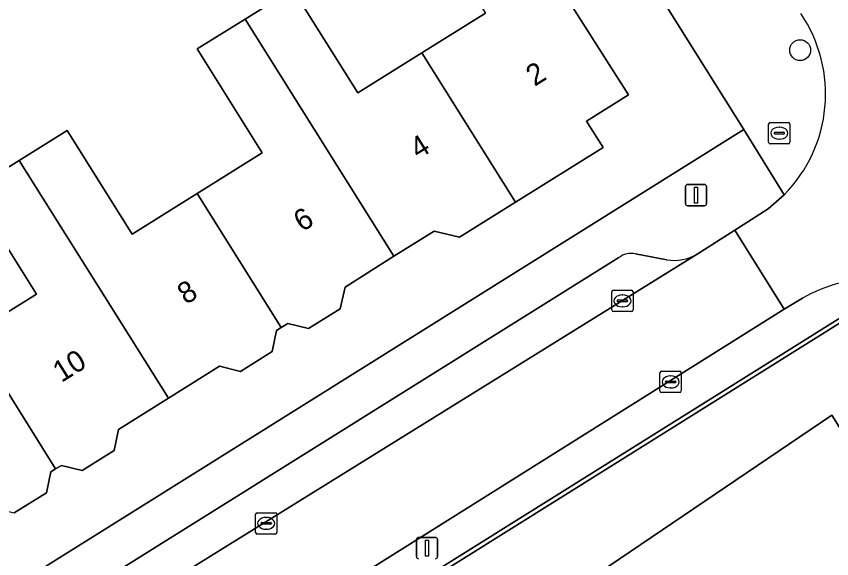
# Model space of a CAD drawing. Extents: x 159664 to 160323, y 385312 to 386115.
# Drawn here: x 159925.33 to 159963.61, y 385804.42 to 385829.91 of the extents above; entities that cross this region are included whole.
import ezdxf

# ---------------------------------------------------------------- set-up
doc = ezdxf.new("R2010")
doc.units = 0
for name, color, linetype in [('IMGEO_Boom', 7, 'Continuous'), ('IMGEO_Brandkraan', 7, 'Continuous'), ('IMGEO_Erf', 7, 'Continuous'), ('IMGEO_Groenvoorziening', 7, 'Continuous'), ('IMGEO_Kolk', 7, 'Continuous'), ('IMGEO_Lichtmast', 7, 'Continuous'), ('IMGEO_Pand', 7, 'Continuous'), ('IMGEO_Pand_nummerreeks', 7, 'Continuous'), ('IMGEO_Parkeervlak_open', 7, 'Continuous'), ('IMGEO_Rijbaan_lokaal_open', 7, 'Continuous'), ('IMGEO_Terreindeel_zand', 7, 'Continuous'), ('IMGEO_Voetpad_open', 7, 'Continuous')]:
    doc.layers.add(name, color=color, linetype=linetype)

msp = doc.modelspace()

# ---------------------------------------------------------------- linework, layer by layer
at = {"layer": 'IMGEO_Boom'}
msp.add_circle((159962.124, 385828.317), 0.489, dxfattribs=at)
at = {"layer": 'IMGEO_Brandkraan'}
for p, q in [((159960.645, 385823.99), (159960.645, 385824.842)), ((159960.72, 385824.916), (159961.572, 385824.916)), ((159961.133, 385824.696), (159961.158, 385824.696)), ((159961.646, 385824.842), (159961.646, 385823.99)), ((159960.904, 385824.41), (159960.904, 385824.422)), ((159961.342, 385824.373), (159960.944, 385824.373)), ((159960.947, 385824.459), (159961.345, 385824.459)), ((159961.388, 385824.422), (159961.388, 385824.41)), ((159961.572, 385823.916), (159960.72, 385823.916)), ((159961.156, 385824.136), (159961.131, 385824.136))]:
    msp.add_line(p, q, dxfattribs=at)
for points in [[(159960.645, 385823.99), (159960.645, 385824.842)], [(159960.72, 385824.916), (159961.572, 385824.916)], [(159961.646, 385824.842), (159961.646, 385823.99)], [(159961.572, 385823.916), (159960.72, 385823.916)]]:
    msp.add_lwpolyline(points, dxfattribs=at)
for centre, radius, start, end in [((159960.722, 385824.84), 0.0765, 91.552, 178.448), ((159960.722, 385824.84), 0.0765, 91.552, 178.448), ((159961.57, 385824.84), 0.0765, 1.552, 88.448), ((159961.57, 385824.84), 0.0765, 1.552, 88.448), ((159960.944, 385824.419), 0.0403, 85.8775, 175.7526), ((159960.941, 385824.409), 0.0366, 178.938, 274.7102), ((159961.345, 385824.416), 0.043, 264.8664, 352.4533), ((159961.349, 385824.421), 0.0386, 1.7309, 96.639), ((159960.722, 385823.992), 0.0765, 181.552, 268.448), ((159960.722, 385823.992), 0.0765, 181.552, 268.448), ((159961.57, 385823.992), 0.0765, 271.552, 358.448), ((159961.57, 385823.992), 0.0765, 271.552, 358.448)]:
    msp.add_arc(centre, radius, start, end, dxfattribs=at)
for centre, major_axis, ratio, start_param, end_param in [((159961.132, 385824.416), (-0.387, 0.002), 0.722429, 4.712389, 7.853982), ((159961.157, 385824.416), (-0.39, 0.002), 0.717154, 1.570796, 4.712389)]:
    msp.add_ellipse(centre, major_axis=major_axis, ratio=ratio, start_param=start_param, end_param=end_param, dxfattribs=at)
at = {"layer": 'IMGEO_Erf'}
for points in [[(159898.799, 385812.12), (159910.257, 385793.769), (159959.474, 385824.596), (159946.689, 385845.008)], [(159948.518, 385834.96), (159954.064, 385826.211), (159952.102, 385824.973), (159952.871, 385823.744), (159948.758, 385821.169), (159946.142, 385819.53), (159944.946, 385819.816), (159943.059, 385818.63), (159940.762, 385817.185), (159940.536, 385816.168), (159939.047, 385815.234), (159938.073, 385815.477), (159937.768, 385815.289), (159937.544, 385815.15), (159937.34, 385814.165), (159935.851, 385813.224), (159934.874, 385813.473), (159932.474, 385811.962), (159930.134, 385810.488), (159929.922, 385809.511), (159928.43, 385808.574), (159927.448, 385808.802), (159927.18, 385808.645), (159926.953, 385808.511), (159926.745, 385807.519), (159925.232, 385806.576)], [(159923.228, 385814.95), (159926.274, 385816.858), (159923.222, 385821.731), (159925.469, 385823.138), (159927.714, 385824.544), (159930.766, 385819.671), (159933.822, 385821.585), (159936.876, 385823.498), (159933.825, 385828.371), (159936.072, 385829.778), (159938.316, 385831.184), (159941.368, 385826.311), (159944.361, 385828.185), (159947.352, 385830.058)]]:
    msp.add_lwpolyline(points, dxfattribs=at)
at = {"layer": 'IMGEO_Groenvoorziening'}
for points in [[(159962.237, 385816.658), (159961.371, 385816.147), (159919.835, 385790.061), (159919.7, 385789.976), (159914.865, 385786.947), (159915.717, 385785.521), (159964.662, 385816.146)], [(159995.344, 385766.743), (159975.15, 385798.647), (159964.547, 385815.857), (159909.705, 385781.51)]]:
    msp.add_lwpolyline(points, dxfattribs=at)
for points in [[(159964.674, 385816.154), (159964.662, 385816.146), (159915.717, 385785.521), (159915.048, 385785.102), (159909.031, 385781.344), (159908.899, 385778.308), (159910.953, 385779.54), (159909.705, 385781.51), (159964.547, 385815.857), (159975.15, 385798.647), (159995.344, 385766.743), (159938.039, 385730.88), (159933.655, 385728.136), (159933.737, 385727.999), (159940.323, 385732.142), (159995.631, 385766.698)], [(159954.246, 385795.242), (159955.408, 385796.027), (159951.163, 385802.729), (159963.604, 385811.166), (159970.471, 385800.247), (159965.618, 385797.02), (159966.505, 385795.588), (159967.641, 385793.756), (159965.549, 385792.301), (159963.92, 385791.167), (159961.742, 385794.443), (159958.086, 385792.013), (159957.032, 385793.455), (159955.83, 385792.745)]]:
    msp.add_lwpolyline(points, close=True, dxfattribs=at)
msp.add_arc((159965.736, 385810.616), 6.982, 104.8122, 120.0758, dxfattribs=at)
at = {"layer": 'IMGEO_Kolk'}
for p, q in [((159953.359, 385817.036), (159954.211, 385817.036)), ((159953.284, 385816.11), (159953.284, 385816.962)), ((159953.772, 385816.816), (159953.797, 385816.816)), ((159954.285, 385816.962), (159954.285, 385816.11)), ((159953.543, 385816.53), (159953.543, 385816.542)), ((159953.981, 385816.493), (159953.583, 385816.493)), ((159953.586, 385816.579), (159953.984, 385816.579)), ((159953.795, 385816.256), (159953.77, 385816.256)), ((159954.027, 385816.542), (159954.027, 385816.53)), ((159954.211, 385816.036), (159953.359, 385816.036)), ((159955.545, 385812.303), (159955.545, 385813.155)), ((159955.62, 385813.229), (159956.472, 385813.229)), ((159956.546, 385813.155), (159956.546, 385812.303)), ((159955.847, 385812.772), (159956.245, 385812.772)), ((159956.033, 385813.009), (159956.058, 385813.009)), ((159955.804, 385812.723), (159955.804, 385812.735)), ((159956.242, 385812.686), (159955.844, 385812.686)), ((159956.056, 385812.449), (159956.031, 385812.449)), ((159956.288, 385812.735), (159956.288, 385812.723)), ((159956.472, 385812.229), (159955.62, 385812.229)), ((159936.561, 385805.658), (159936.561, 385806.51)), ((159936.636, 385806.584), (159937.488, 385806.584)), ((159937.049, 385806.364), (159937.074, 385806.364)), ((159937.562, 385806.51), (159937.562, 385805.658)), ((159936.82, 385806.078), (159936.82, 385806.09)), ((159937.258, 385806.041), (159936.86, 385806.041)), ((159936.863, 385806.127), (159937.261, 385806.127)), ((159937.304, 385806.09), (159937.304, 385806.078)), ((159937.488, 385805.584), (159936.636, 385805.584)), ((159937.072, 385805.804), (159937.047, 385805.804))]:
    msp.add_line(p, q, dxfattribs=at)
for points in [[(159953.359, 385817.036), (159954.211, 385817.036)], [(159953.284, 385816.11), (159953.284, 385816.962)], [(159954.285, 385816.962), (159954.285, 385816.11)], [(159954.211, 385816.036), (159953.359, 385816.036)], [(159955.545, 385812.303), (159955.545, 385813.155)], [(159955.62, 385813.229), (159956.472, 385813.229)], [(159956.546, 385813.155), (159956.546, 385812.303)], [(159956.472, 385812.229), (159955.62, 385812.229)], [(159936.561, 385805.658), (159936.561, 385806.51)], [(159936.636, 385806.584), (159937.488, 385806.584)], [(159937.562, 385806.51), (159937.562, 385805.658)], [(159937.488, 385805.584), (159936.636, 385805.584)]]:
    msp.add_lwpolyline(points, dxfattribs=at)
for centre, radius, start, end in [((159953.361, 385816.96), 0.0765, 91.552, 178.448), ((159953.361, 385816.96), 0.0765, 91.552, 178.448), ((159954.209, 385816.96), 0.0765, 1.552, 88.448), ((159954.209, 385816.96), 0.0765, 1.552, 88.448), ((159953.583, 385816.539), 0.0403, 85.8775, 175.7526), ((159953.58, 385816.529), 0.0366, 178.938, 274.7102), ((159953.984, 385816.536), 0.043, 264.8664, 352.4533), ((159953.988, 385816.541), 0.0386, 1.7309, 96.639), ((159953.361, 385816.112), 0.0765, 181.552, 268.448), ((159953.361, 385816.112), 0.0765, 181.552, 268.448), ((159954.209, 385816.112), 0.0765, 271.552, 358.448), ((159954.209, 385816.112), 0.0765, 271.552, 358.448), ((159955.622, 385813.153), 0.0765, 91.552, 178.448), ((159955.622, 385813.153), 0.0765, 91.552, 178.448), ((159956.47, 385813.153), 0.0765, 1.552, 88.448), ((159956.47, 385813.153), 0.0765, 1.552, 88.448), ((159955.844, 385812.732), 0.0403, 85.8775, 175.7526), ((159956.249, 385812.734), 0.0386, 1.7309, 96.639), ((159955.841, 385812.722), 0.0366, 178.938, 274.7102), ((159956.245, 385812.729), 0.043, 264.8664, 352.4533), ((159955.622, 385812.305), 0.0765, 181.552, 268.448), ((159955.622, 385812.305), 0.0765, 181.552, 268.448), ((159956.47, 385812.305), 0.0765, 271.552, 358.448), ((159956.47, 385812.305), 0.0765, 271.552, 358.448), ((159936.638, 385806.508), 0.0765, 91.552, 178.448), ((159936.638, 385806.508), 0.0765, 91.552, 178.448), ((159937.486, 385806.508), 0.0765, 1.552, 88.448), ((159937.486, 385806.508), 0.0765, 1.552, 88.448), ((159936.86, 385806.087), 0.0403, 85.8775, 175.7526), ((159936.857, 385806.077), 0.0366, 178.938, 274.7102), ((159937.261, 385806.084), 0.043, 264.8664, 352.4533), ((159937.265, 385806.089), 0.0386, 1.7309, 96.639), ((159936.638, 385805.66), 0.0765, 181.552, 268.448), ((159936.638, 385805.66), 0.0765, 181.552, 268.448), ((159937.486, 385805.66), 0.0765, 271.552, 358.448), ((159937.486, 385805.66), 0.0765, 271.552, 358.448)]:
    msp.add_arc(centre, radius, start, end, dxfattribs=at)
for centre, major_axis, ratio, start_param, end_param in [((159953.771, 385816.536), (-0.387, 0.002), 0.722429, 4.712389, 7.853982), ((159953.796, 385816.536), (-0.39, 0.002), 0.717154, 1.570796, 4.712389), ((159956.032, 385812.729), (-0.387, 0.002), 0.722429, 4.712389, 7.853982), ((159956.057, 385812.729), (-0.39, 0.002), 0.717154, 1.570796, 4.712389), ((159937.048, 385806.084), (-0.387, 0.002), 0.722429, 4.712389, 7.853982), ((159937.073, 385806.084), (-0.39, 0.002), 0.717154, 1.570796, 4.712389)]:
    msp.add_ellipse(centre, major_axis=major_axis, ratio=ratio, start_param=start_param, end_param=end_param, dxfattribs=at)
at = {"layer": 'IMGEO_Lichtmast'}
for p, q in [((159956.841, 385822.008), (159957.631, 385822.008)), ((159957.631, 385822.008), (159956.841, 385822.008)), ((159956.741, 385821.108), (159956.741, 385821.908)), ((159956.741, 385821.908), (159956.741, 385821.108)), ((159957.731, 385821.908), (159957.731, 385821.108)), ((159957.731, 385821.108), (159957.731, 385821.908)), ((159957.631, 385821.008), (159956.841, 385821.008)), ((159956.841, 385821.008), (159957.631, 385821.008)), ((159944.117, 385804.523), (159944.117, 385805.323)), ((159944.117, 385805.323), (159944.117, 385804.523)), ((159944.217, 385805.423), (159945.007, 385805.423)), ((159945.007, 385805.423), (159944.217, 385805.423)), ((159945.107, 385805.323), (159945.107, 385804.523)), ((159945.107, 385804.523), (159945.107, 385805.323))]:
    msp.add_line(p, q, dxfattribs=at)
for points in [[(159957.161, 385821.883), (159957.311, 385821.883), (159957.311, 385821.133), (159957.161, 385821.133), (159957.161, 385821.883)], [(159944.537, 385805.298), (159944.687, 385805.298), (159944.687, 385804.548), (159944.537, 385804.548), (159944.537, 385805.298)]]:
    msp.add_lwpolyline(points, dxfattribs=at)
for centre, start, end in [((159956.841, 385821.908), 90, 180), ((159956.841, 385821.908), 90, 180), ((159957.631, 385821.908), 0, 90), ((159957.631, 385821.908), 360, 90), ((159956.841, 385821.108), 180, 270), ((159956.841, 385821.108), 180, 270), ((159957.631, 385821.108), 270, 0), ((159957.631, 385821.108), 270, 0), ((159944.217, 385805.323), 90, 180), ((159944.217, 385805.323), 90, 180), ((159945.007, 385805.323), 0, 90), ((159945.007, 385805.323), 360, 90), ((159944.217, 385804.523), 180, 270), ((159944.217, 385804.523), 180, 270), ((159945.007, 385804.523), 270, 0), ((159945.007, 385804.523), 270, 0)]:
    msp.add_arc(centre, 0.1, start, end, dxfattribs=at)
at = {"layer": 'IMGEO_Pand'}
for points in [[(159948.758, 385821.169), (159952.871, 385823.744), (159952.102, 385824.973), (159954.064, 385826.211), (159948.518, 385834.96), (159945.526, 385832.973), (159947.352, 385830.058), (159944.361, 385828.185)], [(159943.059, 385818.63), (159944.946, 385819.816), (159946.142, 385819.53), (159948.758, 385821.169), (159944.361, 385828.185), (159941.368, 385826.311), (159938.316, 385831.184), (159936.072, 385829.778)], [(159936.072, 385829.778), (159933.825, 385828.371), (159936.876, 385823.498), (159933.822, 385821.585), (159937.768, 385815.289), (159938.073, 385815.477), (159939.047, 385815.234), (159940.536, 385816.168), (159940.762, 385817.185), (159943.059, 385818.63)], [(159932.474, 385811.962), (159934.874, 385813.473), (159935.851, 385813.224), (159937.34, 385814.165), (159937.544, 385815.15), (159937.768, 385815.289), (159933.822, 385821.585), (159930.766, 385819.671), (159927.714, 385824.544), (159925.469, 385823.138)], [(159925.469, 385823.138), (159923.222, 385821.731), (159926.274, 385816.858), (159923.228, 385814.95), (159927.18, 385808.645), (159927.448, 385808.802), (159928.43, 385808.574), (159929.922, 385809.511), (159930.134, 385810.488), (159932.474, 385811.962)], [(159923.228, 385814.95), (159921.522, 385817.672), (159918.476, 385815.763), (159917.128, 385817.915), (159914.884, 385816.509), (159921.894, 385805.324), (159924.277, 385806.818), (159925.232, 385806.576), (159926.745, 385807.519), (159926.953, 385808.511), (159927.18, 385808.645)]]:
    msp.add_lwpolyline(points, close=True, dxfattribs=at)
at = {"layer": 'IMGEO_Parkeervlak_open'}
for points in [[(159953.615, 385818.569), (159919.605, 385797.293), (159919.163, 385797.034), (159919.025, 385796.887), (159918.902, 385796.65), (159918.441, 385795.118), (159918.014, 385794.341), (159957.291, 385818.735)], [(159955.868, 385818.472), (159954.395, 385818.747)]]:
    msp.add_lwpolyline(points, dxfattribs=at)
for centre, radius, start, end in [((159954.197, 385817.818), 0.95, 77.9614, 127.7487), ((159956.224, 385820.525), 2.084, 260.1541, 300.7885)]:
    msp.add_arc(centre, radius, start, end, dxfattribs=at)
at = {"layer": 'IMGEO_Rijbaan_lokaal_open'}
for points in [[(159961.377, 385821.523), (159960.627, 385820.864)], [(159960.627, 385820.864), (159959.055, 385819.861)], [(159959.055, 385819.861), (159961.371, 385816.147)], [(159961.371, 385816.147), (159962.237, 385816.658)]]:
    msp.add_lwpolyline(points, dxfattribs=at)
msp.add_lwpolyline([(159961.371, 385816.147), (159959.055, 385819.861), (159957.291, 385818.735), (159918.014, 385794.341), (159917.361, 385793.935), (159919.835, 385790.061)], close=True, dxfattribs=at)
for centre, radius, start, end in [((159956.571, 385826.257), 6.746, 315.4316, 34.1322), ((159965.736, 385810.616), 6.982, 104.8122, 120.0758)]:
    msp.add_arc(centre, radius, start, end, dxfattribs=at)
at = {"layer": 'IMGEO_Terreindeel_zand'}
msp.add_lwpolyline([(159963.604, 385811.166), (159951.163, 385802.729), (159955.408, 385796.027), (159957.032, 385793.455), (159958.086, 385792.013), (159961.742, 385794.443), (159963.92, 385791.167), (159965.549, 385792.301), (159967.641, 385793.756), (159966.505, 385795.588), (159965.618, 385797.02), (159970.471, 385800.247)], close=True, dxfattribs=at)
at = {"layer": 'IMGEO_Voetpad_open'}
for points in [[(159901.635, 385925.571), (159897.762, 385923.148), (159910.117, 385903.4), (159912.237, 385900.05), (159945.912, 385846.253), (159943.437, 385844.726), (159942.68, 385844.254), (159943.473, 385842.986), (159946.689, 385845.008), (159959.474, 385824.596), (159961.377, 385821.523)], [(159957.291, 385818.735), (159959.055, 385819.861), (159960.627, 385820.864), (159961.377, 385821.523), (159959.474, 385824.596), (159910.257, 385793.769), (159908.63, 385792.179)], [(159915.631, 385792.861), (159917.264, 385793.875), (159917.361, 385793.935), (159918.014, 385794.341), (159918.441, 385795.118), (159918.902, 385796.65), (159919.025, 385796.887), (159919.163, 385797.034), (159919.605, 385797.293), (159953.615, 385818.569)], [(159954.395, 385818.747), (159955.868, 385818.472)]]:
    msp.add_lwpolyline(points, dxfattribs=at)
for centre, radius, start, end in [((159956.571, 385826.257), 6.746, 315.4316, 34.1322), ((159954.197, 385817.818), 0.95, 77.9614, 127.7487), ((159956.224, 385820.525), 2.084, 260.1541, 300.7885)]:
    msp.add_arc(centre, radius, start, end, dxfattribs=at)

# ---------------------------------------------------------------- texts
at = {"layer": 'IMGEO_Pand_nummerreeks'}
for s, p in [('2', (159949.662, 385826.59)), ('4', (159944.208, 385823.172)), ('6', (159938.751, 385819.754)), ('8', (159933.298, 385816.338)), ('10', (159927.451, 385812.676))]:
    msp.add_text(s, height=1, rotation=32.0637, dxfattribs=at).set_placement(p)

doc.saveas('drawing.dxf')
